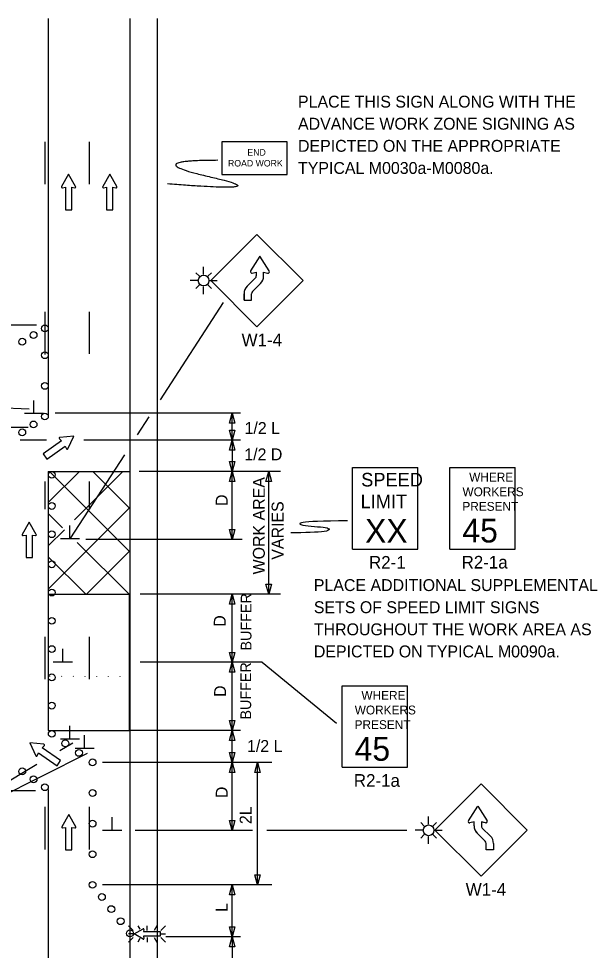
# Model space of a CAD drawing. Extents: x 16525 to 18478, y 5730 to 6925.
# Drawn here: x 17082 to 17422, y 6370 to 6918 of the extents above; entities that cross this region are included whole.
import ezdxf

# ---------------------------------------------------------------- set-up
doc = ezdxf.new("R2010")
doc.units = 0
for name, color, linetype in [('ALI_LEGAL_EX', 7, 'Continuous'), ('Level 3', 7, 'Continuous'), ('MT_SCRATCH_LEVEL_A', 7, 'Continuous'), ('MT_SCRATCH_LEVEL_E', 7, 'Continuous'), ('PAVT_EDGE_EX', 7, 'Continuous'), ('TRAFFIC_SIGNS_PR', 7, 'Continuous'), ('TYPICAL_TEXT_DIMEN_PR', 7, 'Continuous')]:
    doc.layers.add(name, color=color, linetype=linetype)

msp = doc.modelspace()

# ---------------------------------------------------------------- linework, layer by layer
at = {"layer": 'ALI_LEGAL_EX'}
for points in [[(17097.59, 6845.22), (17097.59, 6820.22)], [(17123.59, 6845.22), (17123.59, 6820.22)], [(17097.59, 6745.22), (17097.59, 6720.22)], [(17123.59, 6745.22), (17123.59, 6720.56)], [(17097.59, 6645.4), (17097.59, 6629.22)], [(17123.59, 6645.4), (17123.59, 6629.22)], [(17097.59, 6554.22), (17097.59, 6529.22)], [(17123.59, 6554.22), (17123.59, 6529.22)], [(17097.59, 6454.22), (17097.59, 6429.22)], [(17123.59, 6454.22), (17123.59, 6429.22)]]:
    msp.add_lwpolyline(points, dxfattribs=at)
at = {"layer": 'Level 3'}
msp.add_line((17225.4, 6539.17), (17268.92, 6503.45), dxfattribs=at)
at = {"layer": 'MT_SCRATCH_LEVEL_A'}
for p, q in [((17099.59, 6651.4), (17147.59, 6651.4)), ((17099.59, 6633.05), (17117.94, 6651.4)), ((17147.59, 6604.14), (17100.33, 6651.4)), ((17114.89, 6622.89), (17143.4, 6651.4)), ((17147.59, 6629.6), (17125.78, 6651.4)), ((17099.59, 6582.14), (17147.59, 6630.14)), ((17107.95, 6618.33), (17099.59, 6626.69)), ((17099.59, 6607.59), (17109.02, 6617.02)), ((17147.11, 6579.17), (17116.62, 6609.66)), ((17121.65, 6579.17), (17099.59, 6601.23)), ((17122.07, 6579.17), (17147.59, 6604.68)), ((17099.59, 6531.23), (17099.59, 6531.23)), ((17100.51, 6530.87), (17100.57, 6530.99)), ((17107.4, 6530.87), (17107.46, 6530.99)), ((17114.29, 6530.87), (17114.34, 6530.99)), ((17121.18, 6530.87), (17121.23, 6530.99)), ((17128.06, 6530.87), (17128.12, 6530.99)), ((17134.95, 6530.87), (17135.01, 6530.99)), ((17141.84, 6530.87), (17141.89, 6530.99))]:
    msp.add_line(p, q, dxfattribs=at)
at = {"layer": 'MT_SCRATCH_LEVEL_E'}
for p, q in [((17111.52, 6826.05), (17107.41, 6818.81)), ((17111.52, 6826.05), (17107.41, 6818.81)), ((17115.67, 6818.81), (17111.52, 6826.05)), ((17115.67, 6818.81), (17111.52, 6826.05)), ((17135.69, 6826.05), (17131.58, 6818.81)), ((17135.69, 6826.05), (17131.58, 6818.81)), ((17139.84, 6818.81), (17135.69, 6826.05)), ((17139.84, 6818.81), (17135.69, 6826.05)), ((17107.89, 6818.12), (17109.67, 6818.44)), ((17107.89, 6818.12), (17109.67, 6818.44)), ((17109.67, 6818.44), (17109.67, 6805.18)), ((17109.67, 6818.44), (17109.67, 6805.18)), ((17113.41, 6805.18), (17113.41, 6818.44)), ((17113.41, 6818.44), (17115.19, 6818.12)), ((17113.41, 6805.18), (17113.41, 6818.44)), ((17113.41, 6818.44), (17115.19, 6818.12)), ((17132.06, 6818.12), (17133.84, 6818.44)), ((17132.06, 6818.12), (17133.84, 6818.44)), ((17133.84, 6818.44), (17133.84, 6805.18)), ((17133.84, 6818.44), (17133.84, 6805.18)), ((17137.58, 6805.18), (17137.58, 6818.44)), ((17137.58, 6818.44), (17139.36, 6818.12)), ((17137.58, 6805.18), (17137.58, 6818.44)), ((17137.58, 6818.44), (17139.36, 6818.12)), ((17109.67, 6805.18), (17113.41, 6805.18)), ((17109.67, 6805.18), (17113.41, 6805.18)), ((17133.84, 6805.18), (17137.58, 6805.18)), ((17133.84, 6805.18), (17137.58, 6805.18)), ((17114.69, 6672.2), (17106.4, 6671.43)), ((17114.69, 6672.2), (17106.4, 6671.43)), ((17111.13, 6664.66), (17114.69, 6672.2)), ((17111.13, 6664.66), (17114.69, 6672.2)), ((17107.39, 6669.36), (17096.52, 6661.77)), ((17107.39, 6669.36), (17096.52, 6661.77)), ((17098.66, 6658.7), (17109.53, 6666.3)), ((17098.66, 6658.7), (17109.53, 6666.3)), ((17106.11, 6670.64), (17107.39, 6669.36)), ((17106.11, 6670.64), (17107.39, 6669.36)), ((17109.53, 6666.3), (17110.29, 6664.66)), ((17109.53, 6666.3), (17110.29, 6664.66)), ((17096.52, 6661.77), (17098.66, 6658.7)), ((17096.52, 6661.77), (17098.66, 6658.7)), ((17088.36, 6621.59), (17084.25, 6614.35)), ((17088.36, 6621.59), (17084.25, 6614.35)), ((17092.5, 6614.35), (17088.36, 6621.59)), ((17092.5, 6614.35), (17088.36, 6621.59)), ((17084.73, 6613.66), (17086.51, 6613.98)), ((17084.73, 6613.66), (17086.51, 6613.98)), ((17086.51, 6613.98), (17086.51, 6600.72)), ((17086.51, 6613.98), (17086.51, 6600.72)), ((17090.25, 6600.72), (17090.25, 6613.98)), ((17090.25, 6613.98), (17092.03, 6613.66)), ((17090.25, 6600.72), (17090.25, 6613.98)), ((17090.25, 6613.98), (17092.03, 6613.66)), ((17086.51, 6600.72), (17090.25, 6600.72)), ((17086.51, 6600.72), (17090.25, 6600.72)), ((17088.66, 6491.79), (17092.24, 6484.28)), ((17096.97, 6491.05), (17088.66, 6491.79)), ((17088.66, 6491.79), (17092.24, 6484.28)), ((17096.97, 6491.05), (17088.66, 6491.79)), ((17093.08, 6484.28), (17093.84, 6485.92)), ((17093.08, 6484.28), (17093.84, 6485.92)), ((17093.84, 6485.92), (17104.71, 6478.33)), ((17093.84, 6485.92), (17104.71, 6478.33)), ((17095.98, 6488.99), (17097.26, 6490.26)), ((17095.98, 6488.99), (17097.26, 6490.26)), ((17106.85, 6481.4), (17095.98, 6488.99)), ((17106.85, 6481.4), (17095.98, 6488.99)), ((17104.71, 6478.33), (17106.85, 6481.4)), ((17104.71, 6478.33), (17106.85, 6481.4)), ((17111.61, 6449.74), (17107.5, 6442.5)), ((17111.61, 6449.74), (17107.5, 6442.5)), ((17115.76, 6442.5), (17111.61, 6449.74)), ((17115.76, 6442.5), (17111.61, 6449.74)), ((17107.99, 6441.82), (17109.76, 6442.13)), ((17107.99, 6441.82), (17109.76, 6442.13)), ((17109.76, 6442.13), (17109.76, 6428.88)), ((17109.76, 6442.13), (17109.76, 6428.88)), ((17113.5, 6428.88), (17113.5, 6442.13)), ((17113.5, 6442.13), (17115.28, 6441.82)), ((17113.5, 6428.88), (17113.5, 6442.13)), ((17113.5, 6442.13), (17115.28, 6441.82)), ((17109.76, 6428.88), (17113.5, 6428.88)), ((17109.76, 6428.88), (17113.5, 6428.88))]:
    msp.add_line(p, q, dxfattribs=at)
for centre, start, end in [((17107.82, 6818.58), 150.4248, 279.9638), ((17107.82, 6818.58), 150.4248, 279.9638), ((17115.26, 6818.58), 260.0362, 29.7731), ((17115.26, 6818.58), 260.0362, 29.7731), ((17131.99, 6818.58), 150.4248, 279.9638), ((17131.99, 6818.58), 150.4248, 279.9638), ((17139.43, 6818.58), 260.0362, 29.7731), ((17139.43, 6818.58), 260.0362, 29.7731), ((17106.45, 6670.96), 95.3561, 224.895), ((17106.45, 6670.96), 95.3561, 224.895), ((17110.71, 6664.86), 204.9674, 334.7043), ((17110.71, 6664.86), 204.9674, 334.7043), ((17084.65, 6614.12), 150.4248, 279.9638), ((17084.65, 6614.12), 150.4248, 279.9638), ((17092.09, 6614.12), 260.0362, 29.7731), ((17092.09, 6614.12), 260.0362, 29.7731), ((17096.92, 6490.58), 315.105, 84.8419), ((17096.92, 6490.58), 315.105, 84.8419), ((17092.66, 6484.48), 205.4936, 335.0326), ((17092.66, 6484.48), 205.4936, 335.0326), ((17107.91, 6442.28), 150.4248, 279.9638), ((17107.91, 6442.28), 150.4248, 279.9638), ((17115.35, 6442.28), 260.0362, 29.7731), ((17115.35, 6442.28), 260.0362, 29.7731)]:
    msp.add_arc(centre, 0.463, start, end, dxfattribs=at)
at = {"layer": 'PAVT_EDGE_EX'}
for p, q in [((17099.59, 6917.57), (17099.59, 6682.86)), ((17147.59, 6917.57), (17147.59, 6063.18)), ((17163.59, 6917.57), (17163.59, 6063.18)), ((17099.59, 6651.4), (17099.59, 6499.17)), ((17099.59, 6464.33), (17099.59, 6063.18))]:
    msp.add_line(p, q, dxfattribs=at)
msp.add_lwpolyline([(17147.26, 6579.04), (17099.59, 6579.04), (17099.59, 6499.17), (17147.26, 6499.17)], close=True, dxfattribs=at)
at = {"layer": 'TRAFFIC_SIGNS_PR'}
for p, q in [((17222.22, 6790.7), (17195.07, 6763.54)), ((17249.37, 6763.54), (17222.22, 6790.7)), ((17190.9, 6767.13), (17190.9, 6771.63)), ((17188.39, 6766.09), (17186.28, 6768.2)), ((17193.41, 6766.09), (17195.52, 6768.2)), ((17216.56, 6760.29), (17221.28, 6765.01)), ((17221.28, 6765), (17216.56, 6760.29)), ((17187.75, 6763.58), (17182.91, 6763.58)), ((17188.39, 6761.06), (17186.28, 6758.95)), ((17190.9, 6755.61), (17190.9, 6760.02)), ((17193.41, 6761.06), (17195.52, 6758.96)), ((17194.06, 6763.58), (17198.94, 6763.58)), ((17195.07, 6763.54), (17222.22, 6736.39)), ((17219.61, 6757.24), (17224.33, 6761.95)), ((17219.62, 6757.24), (17224.33, 6761.95)), ((17222.22, 6736.39), (17249.37, 6763.54)), ((17214.7, 6752.17), (17214.7, 6755.87)), ((17219.01, 6752.17), (17219.01, 6755.87)), ((17214.7, 6752.17), (17219.01, 6752.17)), ((17278.5, 6653.68), (17316.9, 6653.68)), ((17278.5, 6605.68), (17278.5, 6653.68)), ((17316.9, 6605.68), (17316.9, 6653.68)), ((17335.69, 6653.76), (17374.09, 6653.76)), ((17335.69, 6605.76), (17335.69, 6653.76)), ((17374.09, 6605.76), (17374.09, 6653.76)), ((17278.5, 6605.68), (17316.9, 6605.68)), ((17335.69, 6605.76), (17374.09, 6605.76)), ((17272.34, 6525.45), (17310.74, 6525.45)), ((17272.34, 6477.45), (17272.34, 6525.45)), ((17310.74, 6477.45), (17310.74, 6525.45)), ((17272.34, 6477.45), (17310.74, 6477.45)), ((17326.81, 6440.53), (17353.97, 6467.68)), ((17381.12, 6440.53), (17353.97, 6467.68)), ((17323.16, 6443.98), (17323.16, 6448.48)), ((17320.64, 6442.94), (17318.54, 6445.05)), ((17325.67, 6442.94), (17327.78, 6445.05)), ((17359.44, 6437.06), (17354.72, 6441.78)), ((17354.72, 6441.78), (17359.44, 6437.06)), ((17320, 6440.42), (17315.17, 6440.42)), ((17320.64, 6437.91), (17318.54, 6435.8)), ((17323.16, 6432.46), (17323.16, 6436.87)), ((17325.67, 6437.91), (17327.78, 6435.8)), ((17326.31, 6440.42), (17331.19, 6440.42)), ((17353.97, 6413.38), (17326.81, 6440.53)), ((17356.39, 6434.01), (17351.67, 6438.73)), ((17356.38, 6434.01), (17351.67, 6438.73)), ((17381.12, 6440.53), (17353.97, 6413.38)), ((17146.72, 6384.32), (17149.54, 6381.51)), ((17152.15, 6384.33), (17153.36, 6382.23)), ((17157.62, 6381.51), (17157.62, 6384.33)), ((17163.41, 6384.33), (17161.78, 6381.51)), ((17165.71, 6381.51), (17168.53, 6384.33)), ((17149.54, 6379.47), (17146.72, 6379.47)), ((17146.72, 6374.62), (17149.54, 6377.44)), ((17153.44, 6376.81), (17152.18, 6374.62)), ((17157.62, 6377.44), (17157.62, 6374.62)), ((17161.76, 6377.44), (17163.39, 6374.62)), ((17165.71, 6379.47), (17168.53, 6379.47)), ((17165.71, 6377.44), (17168.53, 6374.62))]:
    msp.add_line(p, q, dxfattribs=at)
msp.add_lwpolyline([(17201.62, 6825.92), (17240.02, 6825.92), (17240.02, 6845.12), (17201.62, 6845.12)], close=True, dxfattribs=at)
for points in [[(17229.48, 6769.28), (17224, 6777.89), (17218.52, 6769.28)], [(17229.48, 6769.28), (17224, 6777.89), (17218.52, 6769.28)], [(17219.48, 6767.98), (17221.84, 6768.63), (17221.84, 6766.34)], [(17219.48, 6767.98), (17220.31, 6768.21), (17221.84, 6768.63), (17221.84, 6766.34)], [(17226.15, 6766.26), (17226.16, 6768.63), (17228.52, 6767.98)], [(17214.69, 6755.87), (17214.7, 6752.17), (17219.01, 6752.17), (17219.01, 6755.87)], [(17346.52, 6446.05), (17352, 6454.66), (17357.48, 6446.05)], [(17346.52, 6446.05), (17352, 6454.66), (17357.48, 6446.05)], [(17349.85, 6443.04), (17349.84, 6445.4), (17347.48, 6444.75)], [(17349.85, 6443.04), (17349.84, 6445.4), (17347.48, 6444.75)], [(17356.52, 6444.75), (17354.16, 6445.4), (17354.16, 6443.11)], [(17356.52, 6444.75), (17355.69, 6444.98), (17354.16, 6445.4), (17354.16, 6443.11)], [(17361.31, 6432.64), (17361.3, 6428.94), (17356.99, 6428.94), (17356.99, 6432.64)], [(17155.3, 6376.46), (17149.99, 6379.47), (17155.3, 6382.52)], [(17155.8, 6382.16), (17155.57, 6380.86), (17165.29, 6380.86), (17165.29, 6378.12), (17155.57, 6378.12), (17155.8, 6376.81)]]:
    msp.add_lwpolyline(points, dxfattribs=at)
for centre, radius in [((17190.9, 6763.58), 3.15), ((17097.59, 6735.47), 2), ((17090.92, 6731.56), 2), ((17084.26, 6727.64), 2), ((17097.59, 6719.69), 2), ((17097.59, 6701.69), 2), ((17097.59, 6683.69), 2), ((17090.92, 6679.03), 2), ((17084.26, 6674.37), 2), ((17101.61, 6649.4), 2), ((17101.61, 6631.09), 2), ((17101.61, 6614.48), 2), ((17101.61, 6596.79), 2), ((17101.61, 6580.18), 2), ((17101.61, 6563.56), 2), ((17101.61, 6546.95), 2), ((17101.61, 6530.34), 2), ((17101.61, 6513.73), 2), ((17101.61, 6497.12), 2), ((17109.61, 6491.53), 2), ((17117.61, 6485.94), 2), ((17125.61, 6480.36), 2), ((17084.26, 6475.06), 2), ((17090.92, 6470.41), 2), ((17097.59, 6465.75), 2), ((17125.61, 6462.36), 2), ((17125.61, 6444.36), 2), ((17323.16, 6440.42), 3.15), ((17125.61, 6426.36), 2), ((17125.61, 6408.36), 2), ((17131.11, 6401.22), 2), ((17136.61, 6394.1), 2), ((17142.1, 6386.97), 2), ((17147.6, 6379.84), 2)]:
    msp.add_circle(centre, radius, dxfattribs=at)
for centre, radius, start, end in [((17219.25, 6768.82), 0.864, 147.5204, 285.3986), ((17219.25, 6768.82), 0.866, 147.5288, 285.3852), ((17219.99, 6766.33), 1.85, 314.2123, 0.1238), ((17219.99, 6766.33), 1.85, 314.2125, 0), ((17219.99, 6766.33), 6.17, 314.2125, 359.3819), ((17219.99, 6766.33), 6.17, 314.7687, 359.3755), ((17228.75, 6768.82), 0.866, 254.6799, 32.2804), ((17220.86, 6755.87), 6.17, 134.2117, 180), ((17220.86, 6755.87), 6.17, 134.2125, 180), ((17220.86, 6755.87), 6.17, 134.2125, 180), ((17220.86, 6755.87), 1.85, 132.372, 180), ((17220.86, 6755.87), 1.85, 134.2125, 180), ((17347.25, 6445.59), 0.866, 147.7292, 285.3172), ((17347.25, 6445.59), 0.866, 147.7196, 285.3201), ((17337.41, 6451.85), 10.8, 327.5335, 327.5431), ((17350.33, 6434.33), 10.8, 105.3192, 105.32), ((17356.01, 6443.1), 6.17, 180.6181, 225.7875), ((17356.01, 6443.1), 6.17, 180.6245, 225.2313), ((17356.01, 6443.1), 1.85, 179.8762, 225.7877), ((17356.01, 6443.1), 1.85, 180, 225.7875), ((17356.75, 6445.59), 0.866, 254.6148, 32.4712), ((17355.14, 6432.64), 6.17, 0, 45.7883), ((17355.14, 6432.64), 1.85, 0, 47.628), ((17155.46, 6382.22), 0.341, 350.0407, 118.5167), ((17155.46, 6376.76), 0.341, 241.1084, 9.2692)]:
    msp.add_arc(centre, radius, start, end, dxfattribs=at)
msp.add_open_spline([(17199.27, 6834.28), (17152.03, 6834.28), (17237.05, 6814.94), (17169.72, 6820.43)], degree=2, dxfattribs=at)
at = {"layer": 'TYPICAL_TEXT_DIMEN_PR'}
for p, q in [((17202.33, 6750.69), (17165.28, 6693.5)), ((17092.68, 6737.47), (16962.49, 6737.47)), ((16998.62, 6691.92), (17088.3, 6688.18)), ((17091.13, 6685.38), (17091.13, 6693.17)), ((17096.76, 6685.38), (17085.51, 6685.38)), ((17212.59, 6685.69), (17103.65, 6685.69)), ((17158.75, 6683.41), (17151.91, 6672.85)), ((17206.02, 6679.82), (17207.59, 6685.69)), ((17207.59, 6669.72), (17207.59, 6685.69)), ((17207.59, 6685.69), (17209.16, 6679.82)), ((17087.66, 6677.17), (17076.41, 6677.17)), ((17207.59, 6679.82), (17206.02, 6679.82)), ((17209.16, 6679.82), (17207.59, 6679.82)), ((17207.59, 6669.72), (17206.02, 6675.58)), ((17206.02, 6675.58), (17207.59, 6675.58)), ((17207.59, 6675.58), (17209.16, 6675.58)), ((17209.16, 6675.58), (17207.59, 6669.72)), ((17098.49, 6669.72), (17083.03, 6669.72)), ((17212.59, 6669.72), (17120.57, 6669.72)), ((17206.02, 6663.86), (17207.59, 6669.72)), ((17207.59, 6669.72), (17209.16, 6663.86)), ((17207.59, 6669.72), (17207.59, 6651.4)), ((17144.32, 6661.14), (17112.33, 6611.74)), ((17207.59, 6663.86), (17206.02, 6663.86)), ((17209.16, 6663.86), (17207.59, 6663.86)), ((17207.59, 6651.4), (17206.02, 6657.26)), ((17206.02, 6657.26), (17207.59, 6657.26)), ((17207.59, 6657.26), (17209.16, 6657.26)), ((17209.16, 6657.26), (17207.59, 6651.4)), ((17236.14, 6651.4), (17153.09, 6651.4)), ((17206.02, 6645.54), (17207.59, 6651.4)), ((17207.59, 6611.4), (17207.59, 6651.4)), ((17207.59, 6651.4), (17209.16, 6645.54)), ((17227.56, 6645.54), (17229.13, 6651.4)), ((17229.13, 6579.17), (17229.13, 6651.4)), ((17229.13, 6651.4), (17230.7, 6645.54)), ((17207.59, 6645.54), (17206.02, 6645.54)), ((17209.16, 6645.54), (17207.59, 6645.54)), ((17229.13, 6645.54), (17227.56, 6645.54)), ((17230.7, 6645.54), (17229.13, 6645.54)), ((17112.33, 6611.74), (17112.33, 6619.53)), ((17207.59, 6611.4), (17206.02, 6617.26)), ((17206.02, 6617.26), (17207.59, 6617.26)), ((17207.59, 6617.26), (17209.16, 6617.26)), ((17209.16, 6617.26), (17207.59, 6611.4)), ((17117.95, 6611.74), (17106.7, 6611.74)), ((17213.5, 6611.4), (17121.69, 6611.4)), ((17229.13, 6579.17), (17227.56, 6585.03)), ((17227.56, 6585.03), (17229.13, 6585.03)), ((17229.13, 6585.03), (17230.7, 6585.03)), ((17230.7, 6585.03), (17229.13, 6579.17)), ((17236.14, 6579.17), (17153.54, 6579.17)), ((17206.02, 6573.31), (17207.59, 6579.17)), ((17207.59, 6539.17), (17207.59, 6579.17)), ((17207.59, 6579.17), (17209.16, 6573.31)), ((17207.59, 6573.31), (17206.02, 6573.31)), ((17209.16, 6573.31), (17207.59, 6573.31)), ((17108.09, 6539.26), (17108.09, 6547.04)), ((17207.59, 6539.17), (17206.02, 6545.03)), ((17206.02, 6545.03), (17207.59, 6545.03)), ((17207.59, 6545.03), (17209.16, 6545.03)), ((17209.16, 6545.03), (17207.59, 6539.17)), ((17113.72, 6539.26), (17102.47, 6539.26)), ((17225.4, 6539.17), (17153.54, 6539.17)), ((17206.02, 6533.31), (17207.59, 6539.17)), ((17207.59, 6499.17), (17207.59, 6539.17)), ((17207.59, 6539.17), (17209.16, 6533.31)), ((17207.59, 6533.31), (17206.02, 6533.31)), ((17209.16, 6533.31), (17207.59, 6533.31)), ((17112.33, 6494.1), (17112.33, 6501.89)), ((17207.59, 6499.17), (17206.02, 6505.03)), ((17206.02, 6505.03), (17207.59, 6505.03)), ((17207.59, 6505.03), (17209.16, 6505.03)), ((17209.16, 6505.03), (17207.59, 6499.17)), ((17120.92, 6488.59), (17120.92, 6496.37)), ((17212.59, 6499.17), (17147.59, 6499.17)), ((17206.02, 6493.31), (17207.59, 6499.17)), ((17207.59, 6499.17), (17209.16, 6493.31)), ((17207.59, 6480.36), (17207.59, 6499.17)), ((17106.33, 6487.3), (17113.94, 6491.82)), ((17117.95, 6494.1), (17106.7, 6494.1)), ((17207.59, 6493.31), (17206.02, 6493.31)), ((17209.16, 6493.31), (17207.59, 6493.31)), ((17001.57, 6424.99), (17122.68, 6485.78)), ((17126.55, 6488.59), (17115.3, 6488.59)), ((17207.59, 6480.36), (17206.02, 6486.22)), ((17206.02, 6486.22), (17207.59, 6486.22)), ((17207.59, 6486.22), (17209.16, 6486.22)), ((17209.16, 6486.22), (17207.59, 6480.36)), ((17231.08, 6480.36), (17131.36, 6480.36)), ((17206.02, 6474.49), (17207.59, 6480.36)), ((17207.59, 6440.36), (17207.59, 6480.36)), ((17207.59, 6480.36), (17209.16, 6474.49)), ((17221.02, 6474.49), (17222.59, 6480.36)), ((17222.59, 6408.36), (17222.59, 6480.36)), ((17222.59, 6480.36), (17224.16, 6474.49)), ((17001.57, 6424.99), (17092.92, 6479.32)), ((17207.59, 6474.49), (17206.02, 6474.49)), ((17209.16, 6474.49), (17207.59, 6474.49)), ((17222.59, 6474.49), (17221.02, 6474.49)), ((17224.16, 6474.49), (17222.59, 6474.49)), ((16962.49, 6463.75), (17092.12, 6463.75)), ((17137.09, 6440.28), (17137.09, 6448.06)), ((17207.59, 6440.36), (17206.02, 6446.22)), ((17206.02, 6446.22), (17207.59, 6446.22)), ((17207.59, 6446.22), (17209.16, 6446.22)), ((17209.16, 6446.22), (17207.59, 6440.36)), ((17142.72, 6440.28), (17131.47, 6440.28)), ((17219.61, 6440.36), (17150.56, 6440.36)), ((17310.28, 6440.36), (17228.05, 6440.36)), ((17222.59, 6408.36), (17221.02, 6414.22)), ((17221.02, 6414.22), (17222.59, 6414.22)), ((17222.59, 6414.22), (17224.16, 6414.22)), ((17224.16, 6414.22), (17222.59, 6408.36)), ((17231.08, 6408.36), (17131.36, 6408.36)), ((17206.02, 6402.49), (17207.59, 6408.36)), ((17207.59, 6377.84), (17207.59, 6408.36)), ((17207.59, 6408.36), (17209.16, 6402.49)), ((17207.59, 6402.49), (17206.02, 6402.49)), ((17209.16, 6402.49), (17207.59, 6402.49)), ((17207.59, 6377.84), (17206.02, 6383.7)), ((17206.02, 6383.7), (17207.59, 6383.7)), ((17207.59, 6383.7), (17209.16, 6383.7)), ((17209.16, 6383.7), (17207.59, 6377.84)), ((17212.59, 6377.84), (17168.6, 6377.84)), ((17206.02, 6371.98), (17207.59, 6377.84)), ((17207.59, 6377.84), (17207.59, 6337.84)), ((17207.59, 6377.84), (17209.16, 6371.98)), ((17207.59, 6371.98), (17206.02, 6371.98)), ((17209.16, 6371.98), (17207.59, 6371.98))]:
    msp.add_line(p, q, dxfattribs=at)
msp.add_open_spline([(17275.57, 6622.31), (17244.69, 6622.34), (17246.47, 6618.97), (17265.61, 6618.97), (17265.61, 6615.62), (17250.29, 6615.37), (17242.12, 6615.28)], degree=3, dxfattribs=at)

# ---------------------------------------------------------------- texts
at = {"layer": 'TRAFFIC_SIGNS_PR'}
for s, height, p in [('PLACE THIS SIGN ALONG WITH THE', 7, (17246.38, 6865.29)), ('ADVANCE WORK ZONE SIGNING AS', 7, (17246.38, 6852.29)), ('DEPICTED ON THE APPROPRIATE', 7, (17246.38, 6839.29)), ('END', 3.831, (17216.62, 6837.05)), ('ROAD WORK', 3.831, (17205.23, 6830.66)), ('TYPICAL M0030a-M0080a.', 7, (17246.38, 6826.29)), ('W1-4', 7.44, (17213.22, 6724.95)), ('SPEED', 8, (17283.53, 6642.54)), ('WHERE', 5.2, (17347, 6645.45)), ('WORKERS', 5.2, (17343.07, 6636.85)), ('LIMIT', 8, (17283.2, 6629.74)), ('PRESENT', 5.2, (17343.01, 6628.25)), ('XX', 14.031, (17285.8, 6609.43)), ('45', 14.031, (17343, 6609.62)), ('R2-1', 7.44, (17288.1, 6594.24)), ('R2-1a', 7.44, (17342.54, 6594.32)), ('PLACE ADDITIONAL SUPPLEMENTAL', 7, (17255.69, 6581.07)), ('SETS OF SPEED LIMIT SIGNS', 7, (17255.69, 6568.07)), ('THROUGHOUT THE WORK AREA AS', 7, (17255.69, 6555.07)), ('DEPICTED ON TYPICAL M0090a.', 7, (17255.69, 6542.07)), ('WHERE', 5.2, (17283.65, 6517.14)), ('WORKERS', 5.2, (17279.73, 6508.54)), ('PRESENT', 5.2, (17279.66, 6499.94)), ('45', 14.031, (17279.65, 6481.31)), ('R2-1a', 7.44, (17279.2, 6466.01)), ('W1-4', 7.44, (17344.97, 6401.94))]:
    msp.add_text(s, height=height, dxfattribs=at).set_placement(p)
at = {"layer": 'TYPICAL_TEXT_DIMEN_PR'}
for s, p in [('1/2 L', (17214.94, 6673.41)), ('1/2 D', (17214.8, 6657.93)), ('1/2 L', (17216.41, 6486.5))]:
    msp.add_text(s, height=7, dxfattribs=at).set_placement(p)
for s, height, p in [('WORK AREA', 7, (17226.87, 6590.86)), ('D', 7, (17205.03, 6631.09)), ('VARIES', 7, (17237.87, 6599.5)), ('BUFFER', 6.3, (17219.01, 6546.12)), ('D', 7, (17203.88, 6560.09)), ('BUFFER', 6.3, (17218.82, 6505.53)), ('D', 7, (17204.07, 6518.82)), ('D', 7, (17205.03, 6459.34)), ('2L', 7, (17219.09, 6444.06)), ('L', 7, (17205.03, 6392.46))]:
    msp.add_text(s, height=height, rotation=90, dxfattribs=at).set_placement(p)

doc.saveas('drawing.dxf')
